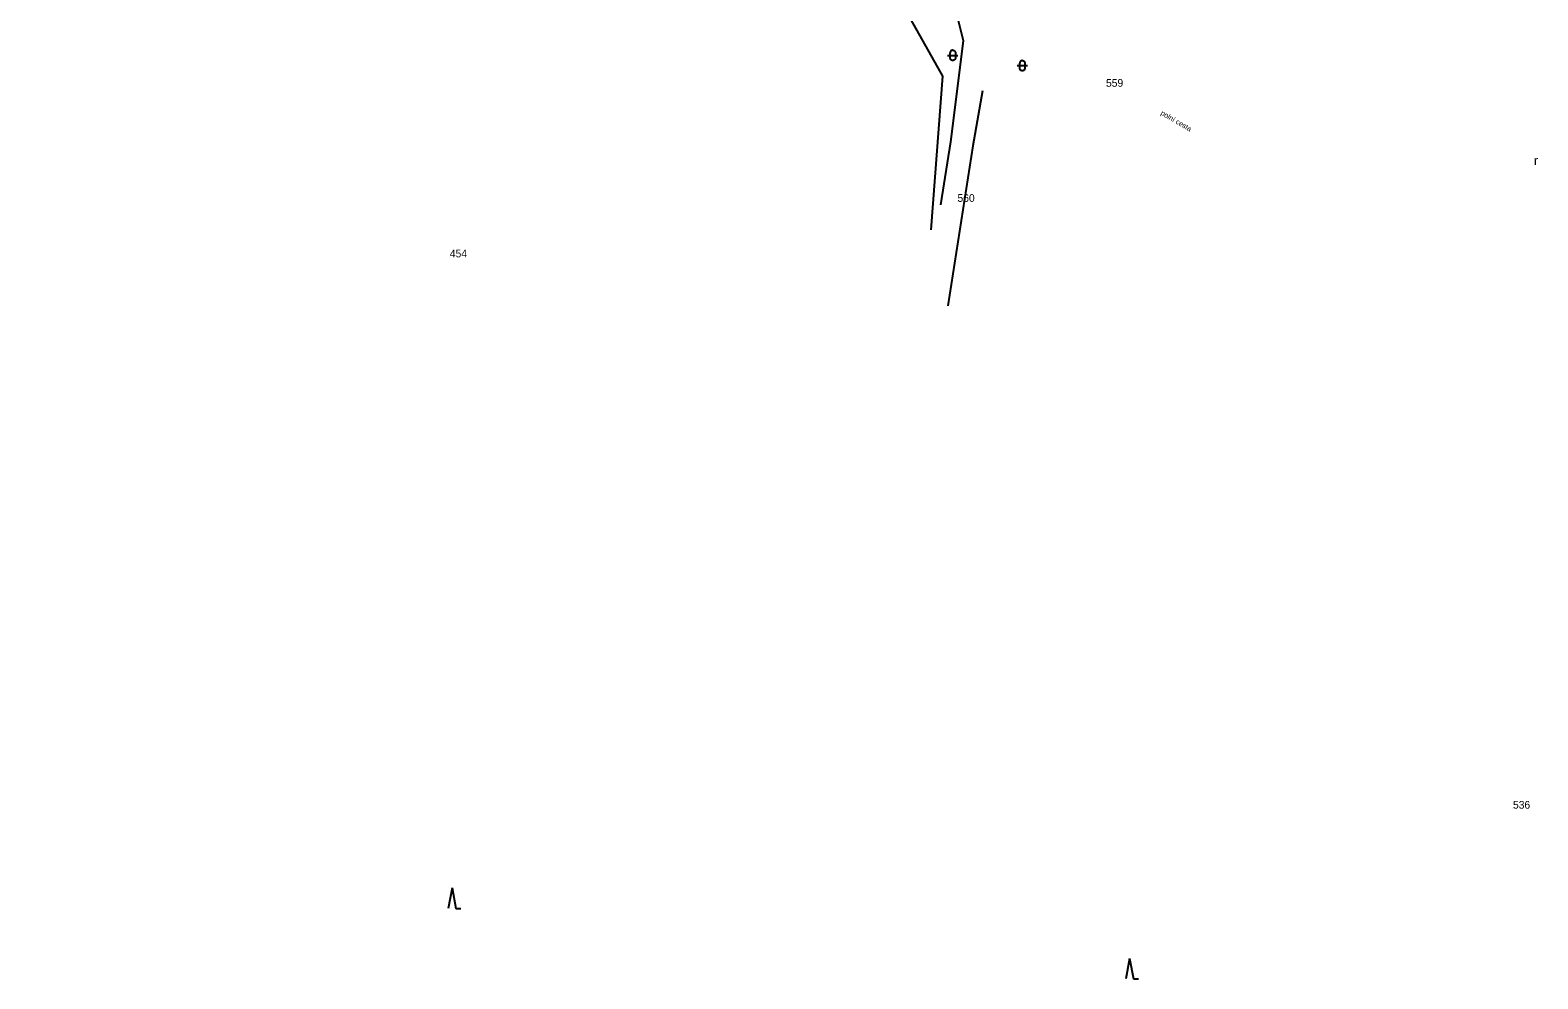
# Model space of a CAD drawing. Extents: x -836739 to -835945, y -1070775 to -1070126.
# Drawn here: x -836135.3 to -835988.4, y -1070619.8 to -1070527.3 of the extents above; entities that cross this region are included whole.
import ezdxf

# ---------------------------------------------------------------- set-up
doc = ezdxf.new("R2010")
doc.units = 0
for name, color, linetype in [('BodPole_mer', 7, 'Continuous'), ('Doprava_hranice', 7, 'Continuous'), ('Doprava_popis', 7, 'Continuous'), ('OstPloch_hranice', 7, 'Continuous'), ('OstPloch_kody', 7, 'Continuous'), ('RuianPar_popis', 7, 'Continuous')]:
    doc.layers.add(name, color=color, linetype=linetype)

msp = doc.modelspace()

# ---------------------------------------------------------------- linework, layer by layer
at = {"layer": 'BodPole_mer'}
for p, q in [((-836044.38, -1070528.39), (-836044.38, -1070528.39)), ((-836046.42, -1070531.83), (-836046.42, -1070531.83)), ((-836042.55, -1070533.25), (-836042.55, -1070533.25)), ((-836045.64, -1070538.23), (-836045.64, -1070538.23)), ((-836043.48, -1070538.62), (-836043.48, -1070538.62)), ((-836046.6, -1070544.35), (-836046.6, -1070544.35)), ((-836047.55, -1070546.79), (-836047.55, -1070546.79)), ((-836045.92, -1070554.2), (-836045.92, -1070554.2))]:
    msp.add_line(p, q, dxfattribs=at)
at = {"layer": 'Doprava_hranice'}
for points in [[(-836046.6, -1070544.35), (-836045.64, -1070538.23), (-836044.38, -1070528.39), (-836045.14, -1070525.37), (-836047.92, -1070523.71), (-836112.97, -1070490.6), (-836124.66, -1070486.54), (-836132.47, -1070484.33), (-836212.77, -1070463.28), (-836247.95, -1070452.55), (-836280.73, -1070441.12), (-836361.89, -1070409.63)], [(-836042.55, -1070533.25), (-836043.48, -1070538.62), (-836045.92, -1070554.2)]]:
    msp.add_lwpolyline(points, dxfattribs=at)
at = {"layer": 'OstPloch_hranice'}
msp.add_lwpolyline([(-836047.55, -1070546.79), (-836046.42, -1070531.83), (-836049.49, -1070526.32), (-836114.97, -1070492.57), (-836125.66, -1070488.35), (-836132.47, -1070484.33)], dxfattribs=at)
at = {"layer": 'OstPloch_kody'}
for p, q in [((-836045.94, -1070529.79), (-836044.94, -1070529.79)), ((-836045.69, -1070530.04), (-836045.69, -1070529.54)), ((-836045.19, -1070529.54), (-836045.19, -1070530.04)), ((-836039.17, -1070530.79), (-836038.17, -1070530.79)), ((-836038.92, -1070531.04), (-836038.92, -1070530.54)), ((-836038.42, -1070530.54), (-836038.42, -1070531.04)), ((-836094.23, -1070610.94), (-836094.6, -1070612.94)), ((-836094.23, -1070610.94), (-836093.86, -1070612.94)), ((-836093.86, -1070612.94), (-836093.36, -1070612.94)), ((-836028.21, -1070617.81), (-836028.58, -1070619.81)), ((-836028.21, -1070617.81), (-836027.84, -1070619.81)), ((-836027.84, -1070619.81), (-836027.34, -1070619.81))]:
    msp.add_line(p, q, dxfattribs=at)
for points in [[(-836045.44, -1070529.29), (-836045.49, -1070529.29), (-836045.53, -1070529.31), (-836045.58, -1070529.33), (-836045.62, -1070529.36), (-836045.65, -1070529.4), (-836045.67, -1070529.45), (-836045.69, -1070529.49), (-836045.69, -1070529.54)], [(-836045.44, -1070529.29), (-836045.39, -1070529.29), (-836045.35, -1070529.31), (-836045.3, -1070529.33), (-836045.26, -1070529.36), (-836045.23, -1070529.4), (-836045.21, -1070529.45), (-836045.19, -1070529.49), (-836045.19, -1070529.54)], [(-836045.44, -1070530.29), (-836045.49, -1070530.29), (-836045.53, -1070530.27), (-836045.58, -1070530.25), (-836045.62, -1070530.22), (-836045.65, -1070530.18), (-836045.67, -1070530.13), (-836045.69, -1070530.09), (-836045.69, -1070530.04)], [(-836045.19, -1070530.04), (-836045.19, -1070530.09), (-836045.21, -1070530.13), (-836045.23, -1070530.18), (-836045.26, -1070530.22), (-836045.3, -1070530.25), (-836045.35, -1070530.27), (-836045.39, -1070530.29), (-836045.44, -1070530.29)], [(-836038.67, -1070530.29), (-836038.72, -1070530.29), (-836038.76, -1070530.31), (-836038.81, -1070530.33), (-836038.85, -1070530.36), (-836038.88, -1070530.4), (-836038.9, -1070530.45), (-836038.92, -1070530.49), (-836038.92, -1070530.54)], [(-836038.67, -1070531.29), (-836038.72, -1070531.29), (-836038.76, -1070531.27), (-836038.81, -1070531.25), (-836038.85, -1070531.22), (-836038.88, -1070531.18), (-836038.9, -1070531.13), (-836038.92, -1070531.09), (-836038.92, -1070531.04)], [(-836038.67, -1070530.29), (-836038.62, -1070530.29), (-836038.58, -1070530.31), (-836038.53, -1070530.33), (-836038.49, -1070530.36), (-836038.46, -1070530.4), (-836038.44, -1070530.45), (-836038.42, -1070530.49), (-836038.42, -1070530.54)], [(-836038.42, -1070531.04), (-836038.42, -1070531.09), (-836038.44, -1070531.13), (-836038.46, -1070531.18), (-836038.49, -1070531.22), (-836038.53, -1070531.25), (-836038.58, -1070531.27), (-836038.62, -1070531.29), (-836038.67, -1070531.29)]]:
    msp.add_lwpolyline(points, dxfattribs=at)
at = {"layer": 'RuianPar_popis'}
for p, q in [((-836030.51, -1070532.85), (-836030.51, -1070532.85)), ((-836044.98, -1070544.07), (-836044.98, -1070544.07)), ((-836094.44, -1070549.48), (-836094.44, -1070549.48)), ((-835990.86, -1070603.22), (-835990.86, -1070603.22))]:
    msp.add_line(p, q, dxfattribs=at)

# ---------------------------------------------------------------- texts
at = {"layer": 'Doprava_popis'}
msp.add_text('polní cesta', height=0.5, rotation=329.76, dxfattribs=at).set_placement((-836025.24, -1070535.55))
at = {"layer": 'OstPloch_kody'}
msp.add_text('r', height=0.9, dxfattribs=at).set_placement((-835988.82, -1070540.49))
at = {"layer": 'RuianPar_popis'}
for s, p in [('559', (-836030.51, -1070532.85)), ('560', (-836044.98, -1070544.07)), ('454', (-836094.44, -1070549.48)), ('536', (-835990.86, -1070603.22))]:
    msp.add_text(s, height=0.75, dxfattribs=at).set_placement(p)

doc.saveas('drawing.dxf')
